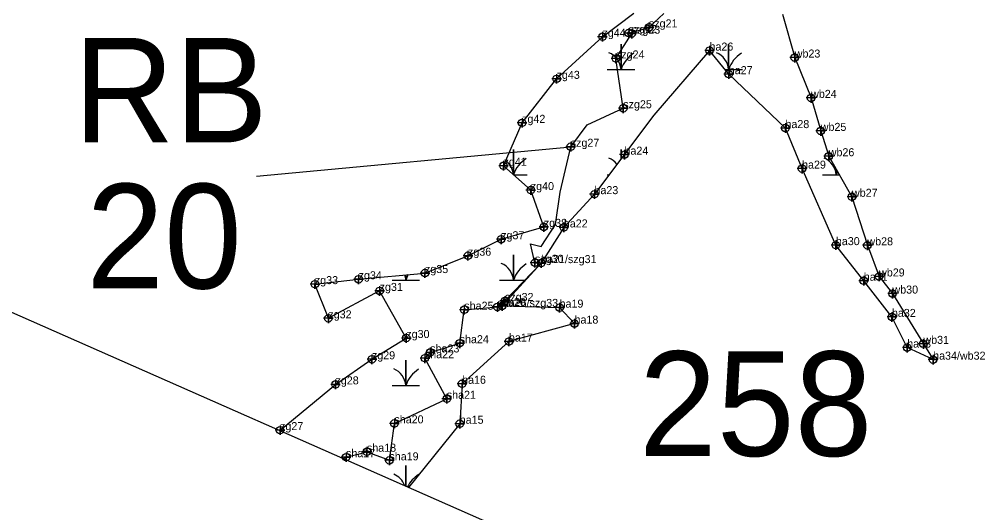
# Model space of a CAD drawing. Extents: x 2071991 to 2268989, y 436479 to 469629.
# Drawn here: x 2217397 to 2217992, y 438334 to 438642 of the extents above; entities that cross this region are included whole.
import ezdxf

# ---------------------------------------------------------------- set-up
doc = ezdxf.new("R2010")
doc.units = 0
for name, color, linetype in [('approx_PSA', 7, 'Continuous'), ('Default', 7, 'Continuous'), ('Exist Environmental Wetland Boundary', 7, 'Continuous'), ('Exist Environmental Wetland Boundary Cogo Comment', 7, 'Continuous'), ('Exist Environmental Wetland Boundary Cogo Point CELL', 7, 'Continuous'), ('Exist Hydro Jurisdictional Stream or Body of Water NEU Mitigable', 7, 'Continuous'), ('Exist Hydro Jurisdictional Stream or Body of Water NEU Mitigable Cogo Comment', 7, 'Continuous'), ('Exist Hydro Jurisdictional Stream or Body of Water NEU Mitigable Cogo Point CELL', 7, 'Continuous'), ('Exist Hydro Swamp or Marsh', 7, 'Continuous')]:
    doc.layers.add(name, color=color, linetype=linetype)

msp = doc.modelspace()

# ---------------------------------------------------------------- linework, layer by layer
at = {"layer": 'approx_PSA'}
msp.add_line((2217940.85, 438216.78), (2217222.14, 438533.73), dxfattribs=at)
at = {"layer": 'Default'}
msp.add_line((2217544.84, 438543.82), (2217741.11, 438562.25), dxfattribs=at)
at = {"layer": 'Exist Environmental Wetland Boundary'}
for points in [[(2217559.29, 438385.05), (2217559.58, 438385.27), (2217594.21, 438413.84), (2217616.96, 438429.52), (2217638.44, 438442.8), (2217621.77, 438472.21), (2217589.75, 438455.1), (2217581.34, 438476.45), (2217608.66, 438479.49), (2217650.1, 438483.36), (2217676.96, 438494.19), (2217697.67, 438504.47), (2217724.32, 438512.19), (2217716.18, 438535.18), (2217699.13, 438550.35), (2217710.75, 438577.17), (2217732.28, 438604.63), (2217760.94, 438630.93), (2217780.52, 438645.68)], [(2217873.28, 438645.11), (2217881.02, 438617.93), (2217891.24, 438592.74), (2217897.26, 438572.14), (2217902.25, 438556.31), (2217916.77, 438530.99), (2217926.41, 438500.68), (2217933.69, 438481.24), (2217942.06, 438470.55), (2217961.38, 438439.14), (2217967.44, 438429.29), (2217951.26, 438436.82), (2217941.72, 438455.97), (2217924.13, 438478.56), (2217906.71, 438500.8), (2217885.6, 438548.57), (2217875.21, 438573.89), (2217839.82, 438607.56), (2217827.79, 438622.29), (2217792.98, 438581.97), (2217755.94, 438532.64), (2217736.81, 438511.86), (2217722.64, 438489.58), (2217698.23, 438462.84), (2217734.16, 438461.77), (2217743.49, 438451.8), (2217702.54, 438440.61), (2217673.28, 438414.22), (2217671.8, 438389.27), (2217639.89, 438349.5)]]:
    msp.add_lwpolyline(points, dxfattribs=at)
at = {"layer": 'Exist Environmental Wetland Boundary Cogo Point CELL'}
for points in [[(2217760.94, 438633.93), (2217760.94, 438627.93), (2217760.94, 438630.93), (2217763.94, 438630.93), (2217757.94, 438630.93)], [(2217827.79, 438625.29), (2217827.79, 438619.29), (2217827.79, 438622.29), (2217830.79, 438622.29), (2217824.79, 438622.29)], [(2217881.02, 438620.93), (2217881.02, 438614.93), (2217881.02, 438617.93), (2217884.02, 438617.93), (2217878.02, 438617.93)], [(2217732.28, 438607.63), (2217732.28, 438601.63), (2217732.28, 438604.63), (2217735.28, 438604.63), (2217729.28, 438604.63)], [(2217839.82, 438610.56), (2217839.82, 438604.56), (2217839.82, 438607.56), (2217842.82, 438607.56), (2217836.82, 438607.56)], [(2217891.24, 438595.74), (2217891.24, 438589.74), (2217891.24, 438592.74), (2217894.24, 438592.74), (2217888.24, 438592.74)], [(2217710.75, 438580.17), (2217710.75, 438574.17), (2217710.75, 438577.17), (2217713.75, 438577.17), (2217707.75, 438577.17)], [(2217875.21, 438576.89), (2217875.21, 438570.89), (2217875.21, 438573.89), (2217878.21, 438573.89), (2217872.21, 438573.89)], [(2217897.26, 438575.14), (2217897.26, 438569.14), (2217897.26, 438572.14), (2217900.26, 438572.14), (2217894.26, 438572.14)], [(2217774.68, 438560.3), (2217774.68, 438554.3), (2217774.68, 438557.3), (2217777.68, 438557.3), (2217771.68, 438557.3)], [(2217902.25, 438559.31), (2217902.25, 438553.31), (2217902.25, 438556.31), (2217905.25, 438556.31), (2217899.25, 438556.31)], [(2217699.13, 438553.35), (2217699.13, 438547.35), (2217699.13, 438550.35), (2217702.13, 438550.35), (2217696.13, 438550.35)], [(2217885.6, 438551.57), (2217885.6, 438545.57), (2217885.6, 438548.57), (2217888.6, 438548.57), (2217882.6, 438548.57)], [(2217716.18, 438538.18), (2217716.18, 438532.18), (2217716.18, 438535.18), (2217719.18, 438535.18), (2217713.18, 438535.18)], [(2217755.94, 438535.64), (2217755.94, 438529.64), (2217755.94, 438532.64), (2217758.94, 438532.64), (2217752.94, 438532.64)], [(2217916.77, 438533.99), (2217916.77, 438527.99), (2217916.77, 438530.99), (2217919.77, 438530.99), (2217913.77, 438530.99)], [(2217724.32, 438515.19), (2217724.32, 438509.19), (2217724.32, 438512.19), (2217727.32, 438512.19), (2217721.32, 438512.19)], [(2217736.81, 438514.86), (2217736.81, 438508.86), (2217736.81, 438511.86), (2217739.81, 438511.86), (2217733.81, 438511.86)], [(2217697.67, 438507.47), (2217697.67, 438501.47), (2217697.67, 438504.47), (2217700.67, 438504.47), (2217694.67, 438504.47)], [(2217906.71, 438503.8), (2217906.71, 438497.8), (2217906.71, 438500.8), (2217909.71, 438500.8), (2217903.71, 438500.8)], [(2217926.41, 438503.68), (2217926.41, 438497.68), (2217926.41, 438500.68), (2217929.41, 438500.68), (2217923.41, 438500.68)], [(2217676.96, 438497.19), (2217676.96, 438491.19), (2217676.96, 438494.19), (2217679.96, 438494.19), (2217673.96, 438494.19)], [(2217722.64, 438492.58), (2217722.64, 438486.58), (2217722.64, 438489.58), (2217725.64, 438489.58), (2217719.64, 438489.58)], [(2217650.1, 438486.36), (2217650.1, 438480.36), (2217650.1, 438483.36), (2217653.1, 438483.36), (2217647.1, 438483.36)], [(2217608.66, 438482.49), (2217608.66, 438476.49), (2217608.66, 438479.49), (2217611.66, 438479.49), (2217605.66, 438479.49)], [(2217924.13, 438481.56), (2217924.13, 438475.56), (2217924.13, 438478.56), (2217927.13, 438478.56), (2217921.13, 438478.56)], [(2217933.69, 438484.24), (2217933.69, 438478.24), (2217933.69, 438481.24), (2217936.69, 438481.24), (2217930.69, 438481.24)], [(2217581.34, 438479.45), (2217581.34, 438473.45), (2217581.34, 438476.45), (2217584.34, 438476.45), (2217578.34, 438476.45)], [(2217621.77, 438475.21), (2217621.77, 438469.21), (2217621.77, 438472.21), (2217624.77, 438472.21), (2217618.77, 438472.21)], [(2217942.06, 438473.55), (2217942.06, 438467.55), (2217942.06, 438470.55), (2217945.06, 438470.55), (2217939.06, 438470.55)], [(2217698.23, 438465.84), (2217698.23, 438459.84), (2217698.23, 438462.84), (2217701.23, 438462.84), (2217695.23, 438462.84)], [(2217734.16, 438464.77), (2217734.16, 438458.77), (2217734.16, 438461.77), (2217737.16, 438461.77), (2217731.16, 438461.77)], [(2217589.75, 438458.1), (2217589.75, 438452.1), (2217589.75, 438455.1), (2217592.75, 438455.1), (2217586.75, 438455.1)], [(2217941.72, 438458.97), (2217941.72, 438452.97), (2217941.72, 438455.97), (2217944.72, 438455.97), (2217938.72, 438455.97)], [(2217743.49, 438454.8), (2217743.49, 438448.8), (2217743.49, 438451.8), (2217746.49, 438451.8), (2217740.49, 438451.8)], [(2217638.44, 438445.8), (2217638.44, 438439.8), (2217638.44, 438442.8), (2217641.44, 438442.8), (2217635.44, 438442.8)], [(2217702.54, 438443.61), (2217702.54, 438437.61), (2217702.54, 438440.61), (2217705.54, 438440.61), (2217699.54, 438440.61)], [(2217951.26, 438439.82), (2217951.26, 438433.82), (2217951.26, 438436.82), (2217954.26, 438436.82), (2217948.26, 438436.82)], [(2217961.38, 438442.14), (2217961.38, 438436.14), (2217961.38, 438439.14), (2217964.38, 438439.14), (2217958.38, 438439.14)], [(2217616.96, 438432.52), (2217616.96, 438426.52), (2217616.96, 438429.52), (2217619.96, 438429.52), (2217613.96, 438429.52)], [(2217967.44, 438432.29), (2217967.44, 438426.29), (2217967.44, 438429.29), (2217970.44, 438429.29), (2217964.44, 438429.29)], [(2217594.21, 438416.84), (2217594.21, 438410.84), (2217594.21, 438413.84), (2217597.21, 438413.84), (2217591.21, 438413.84)], [(2217673.28, 438417.22), (2217673.28, 438411.22), (2217673.28, 438414.22), (2217676.28, 438414.22), (2217670.28, 438414.22)], [(2217671.8, 438392.27), (2217671.8, 438386.27), (2217671.8, 438389.27), (2217674.8, 438389.27), (2217668.8, 438389.27)], [(2217559.58, 438388.27), (2217559.58, 438382.27), (2217559.58, 438385.27), (2217562.58, 438385.27), (2217556.58, 438385.27)]]:
    msp.add_lwpolyline(points, dxfattribs=at)
for centre in [(2217760.94, 438630.93), (2217827.79, 438622.29), (2217881.02, 438617.93), (2217732.28, 438604.63), (2217839.82, 438607.56), (2217891.24, 438592.74), (2217710.75, 438577.17), (2217875.21, 438573.89), (2217897.26, 438572.14), (2217774.68, 438557.3), (2217902.25, 438556.31), (2217699.13, 438550.35), (2217885.6, 438548.57), (2217716.18, 438535.18), (2217755.94, 438532.64), (2217916.77, 438530.99), (2217724.32, 438512.19), (2217736.81, 438511.86), (2217697.67, 438504.47), (2217906.71, 438500.8), (2217926.41, 438500.68), (2217676.96, 438494.19), (2217722.64, 438489.58), (2217608.66, 438479.49), (2217650.1, 438483.36), (2217924.13, 438478.56), (2217933.69, 438481.24), (2217581.34, 438476.45), (2217621.77, 438472.21), (2217942.06, 438470.55), (2217698.23, 438462.84), (2217734.16, 438461.77), (2217589.75, 438455.1), (2217941.72, 438455.97), (2217743.49, 438451.8), (2217638.44, 438442.8), (2217702.54, 438440.61), (2217951.26, 438436.82), (2217961.38, 438439.14), (2217616.96, 438429.52), (2217967.44, 438429.29), (2217594.21, 438413.84), (2217673.28, 438414.22), (2217671.8, 438389.27), (2217559.58, 438385.27)]:
    msp.add_circle(centre, 2.34, dxfattribs=at)
at = {"layer": 'Exist Hydro Jurisdictional Stream or Body of Water NEU Mitigable'}
msp.add_lwpolyline([(2217598.72, 438367.66), (2217600.81, 438368.38), (2217613.85, 438371.78), (2217627.9, 438366.42), (2217631.01, 438389.51), (2217663.72, 438404.86), (2217650.03, 438430.19), (2217653.35, 438433.79), (2217671.77, 438439.56), (2217674.66, 438460.46), (2217695.34, 438462.22), (2217700.03, 438465.94), (2217722.64, 438489.58), (2217718.8, 438489.79), (2217715.94, 438501.57), (2217722.61, 438499.98), (2217731.52, 438513.6), (2217734.44, 438533.91), (2217741.11, 438562.25), (2217751.33, 438575.89), (2217773.92, 438586.27), (2217769.35, 438617.37), (2217779.18, 438632.86), (2217777.31, 438633.2), (2217789.94, 438636.76), (2217799.31, 438645.52)], dxfattribs=at)
at = {"layer": 'Exist Hydro Jurisdictional Stream or Body of Water NEU Mitigable Cogo Point CELL'}
for points in [[(2217777.31, 438636.2), (2217777.31, 438630.2), (2217777.31, 438633.2), (2217780.31, 438633.2), (2217774.31, 438633.2)], [(2217779.18, 438635.86), (2217779.18, 438629.86), (2217779.18, 438632.86), (2217782.18, 438632.86), (2217776.18, 438632.86)], [(2217789.94, 438639.76), (2217789.94, 438633.76), (2217789.94, 438636.76), (2217792.94, 438636.76), (2217786.94, 438636.76)], [(2217769.35, 438620.37), (2217769.35, 438614.37), (2217769.35, 438617.37), (2217772.35, 438617.37), (2217766.35, 438617.37)], [(2217773.92, 438589.27), (2217773.92, 438583.27), (2217773.92, 438586.27), (2217776.92, 438586.27), (2217770.92, 438586.27)], [(2217741.11, 438565.25), (2217741.11, 438559.25), (2217741.11, 438562.25), (2217744.11, 438562.25), (2217738.11, 438562.25)], [(2217718.8, 438492.79), (2217718.8, 438486.79), (2217718.8, 438489.79), (2217721.8, 438489.79), (2217715.8, 438489.79)], [(2217700.03, 438468.94), (2217700.03, 438462.94), (2217700.03, 438465.94), (2217703.03, 438465.94), (2217697.03, 438465.94)], [(2217674.66, 438463.46), (2217674.66, 438457.46), (2217674.66, 438460.46), (2217677.66, 438460.46), (2217671.66, 438460.46)], [(2217695.34, 438465.22), (2217695.34, 438459.22), (2217695.34, 438462.22), (2217698.34, 438462.22), (2217692.34, 438462.22)], [(2217671.77, 438442.56), (2217671.77, 438436.56), (2217671.77, 438439.56), (2217674.77, 438439.56), (2217668.77, 438439.56)], [(2217650.03, 438433.19), (2217650.03, 438427.19), (2217650.03, 438430.19), (2217653.03, 438430.19), (2217647.03, 438430.19)], [(2217653.35, 438436.79), (2217653.35, 438430.79), (2217653.35, 438433.79), (2217656.35, 438433.79), (2217650.35, 438433.79)], [(2217663.72, 438407.86), (2217663.72, 438401.86), (2217663.72, 438404.86), (2217666.72, 438404.86), (2217660.72, 438404.86)], [(2217631.01, 438392.51), (2217631.01, 438386.51), (2217631.01, 438389.51), (2217634.01, 438389.51), (2217628.01, 438389.51)], [(2217613.85, 438374.78), (2217613.85, 438368.78), (2217613.85, 438371.78), (2217616.85, 438371.78), (2217610.85, 438371.78)], [(2217600.81, 438371.38), (2217600.81, 438365.38), (2217600.81, 438368.38), (2217603.81, 438368.38), (2217597.81, 438368.38)], [(2217627.9, 438369.42), (2217627.9, 438363.42), (2217627.9, 438366.42), (2217630.9, 438366.42), (2217624.9, 438366.42)]]:
    msp.add_lwpolyline(points, dxfattribs=at)
for centre in [(2217777.31, 438633.2), (2217779.18, 438632.86), (2217789.94, 438636.76), (2217769.35, 438617.37), (2217773.92, 438586.27), (2217741.11, 438562.25), (2217718.8, 438489.79), (2217674.66, 438460.46), (2217695.34, 438462.22), (2217700.03, 438465.94), (2217671.77, 438439.56), (2217653.35, 438433.79), (2217650.03, 438430.19), (2217663.72, 438404.86), (2217631.01, 438389.51), (2217613.85, 438371.78), (2217600.81, 438368.38), (2217627.9, 438366.42)]:
    msp.add_circle(centre, 2.34, dxfattribs=at)
at = {"layer": 'Exist Hydro Swamp or Marsh'}
for p, q in [((2217705.5, 438544.68), (2217713.93, 438544.68)), ((2217763.93, 438544.68), (2217764.98, 438544.68))]:
    msp.add_line(p, q, dxfattribs=at)
for points in [[(2217763.93, 438610.46), (2217772.53, 438610.46), (2217772.53, 438626.24), (2217772.53, 438610.46), (2217781.13, 438610.46)], [(2217837.45, 438610.46), (2217839.74, 438610.46), (2217839.74, 438626.24), (2217839.74, 438610.46), (2217848.34, 438610.46)], [(2217705.33, 438544.83), (2217705.33, 438560.46), (2217705.33, 438544.83)], [(2217772.53, 438554.74), (2217772.53, 438560.46), (2217772.53, 438554.74)], [(2217898.34, 438544.68), (2217906.94, 438544.68), (2217906.94, 438548.14)], [(2217906.94, 438548.14), (2217906.94, 438544.68), (2217908.92, 438544.68)], [(2217696.73, 438478.9), (2217705.33, 438478.9), (2217705.33, 438494.68), (2217705.33, 438478.9), (2217712.89, 438478.9)], [(2217629.52, 438478.9), (2217638.13, 438478.9), (2217638.13, 438482.24)], [(2217638.13, 438482.24), (2217638.13, 438478.9), (2217646.73, 438478.9)], [(2217629.52, 438413.12), (2217638.13, 438413.12), (2217638.13, 438428.9), (2217638.13, 438413.12), (2217646.73, 438413.12)], [(2217638.13, 438350.28), (2217638.13, 438363.12), (2217638.13, 438350.28)]]:
    msp.add_lwpolyline(points, dxfattribs=at)
for centre, radius, start, end in [((2217760.27, 438609.58), 12.3, 4.14034, 67.53497), ((2217790.77, 438604.4), 19.22, 122.12745, 161.62219), ((2217827.47, 438609.58), 12.3, 4.14034, 67.53497), ((2217857.98, 438604.4), 19.22, 122.12745, 161.62219), ((2217693.06, 438543.79), 12.3, 4.90369, 52.63639), ((2217723.57, 438538.62), 19.22, 122.12745, 161.2546), ((2217760.27, 438543.79), 12.3, 37.83312, 67.53497), ((2217894.67, 438543.79), 12.3, 4.14034, 67.53497), ((2217925.18, 438538.62), 19.22, 155.07473, 161.62219), ((2217693.06, 438478.01), 12.3, 4.14034, 67.53497), ((2217723.57, 438472.84), 19.22, 122.12745, 161.62219), ((2217625.86, 438478.01), 12.3, 4.14034, 19.77671), ((2217656.37, 438472.84), 19.22, 150.23165, 161.62219), ((2217625.86, 438412.23), 12.3, 4.14034, 67.53497), ((2217656.37, 438407.06), 19.22, 122.12745, 161.62219), ((2217625.86, 438346.45), 12.3, 19.60086, 67.53497), ((2217656.37, 438341.28), 19.22, 122.12745, 153.60163)]:
    msp.add_arc(centre, radius, start, end, dxfattribs=at)

# ---------------------------------------------------------------- texts
at = {"layer": 'Default'}
for s, p in [('RB', (2217430.54, 438564.89)), ('20', (2217438.59, 438473.74)), ('258', (2217783.77, 438369.14))]:
    msp.add_text(s, height=65.34, dxfattribs=at).set_placement(p)
at = {"layer": 'Exist Environmental Wetland Boundary Cogo Comment'}
for s, p in [('zg44', (2217760.94, 438630.93)), ('ha26', (2217827.79, 438622.29)), ('wb23', (2217881.02, 438617.93)), ('ha27', (2217839.82, 438607.56)), ('zg43', (2217732.28, 438604.63)), ('wb24', (2217891.24, 438592.74)), ('zg42', (2217710.75, 438577.17)), ('ha28', (2217875.21, 438573.89)), ('wb25', (2217897.26, 438572.14)), ('ha24', (2217774.68, 438557.3)), ('wb26', (2217902.25, 438556.31)), ('zg41', (2217699.13, 438550.35)), ('ha29', (2217885.6, 438548.57)), ('zg40', (2217716.18, 438535.18)), ('ha23', (2217755.94, 438532.64)), ('wb27', (2217916.77, 438530.99)), ('zg37', (2217697.67, 438504.47)), ('ha30', (2217906.71, 438500.8)), ('wb28', (2217926.41, 438500.68)), ('zg36', (2217676.96, 438494.19)), ('szg30', (2217718.8, 438489.79)), ('zg35', (2217650.1, 438483.36)), ('wb29', (2217933.69, 438481.24)), ('zg33', (2217581.34, 438476.45)), ('zg34', (2217608.66, 438479.49)), ('ha31', (2217924.13, 438478.56)), ('zg31', (2217621.77, 438472.21)), ('wb30', (2217942.06, 438470.55)), ('ha20', (2217698.23, 438462.84)), ('ha19', (2217734.16, 438461.77)), ('zg32', (2217589.75, 438455.1)), ('ha18', (2217743.49, 438451.8)), ('ha32', (2217941.72, 438455.97)), ('zg30', (2217638.44, 438442.8)), ('ha17', (2217702.54, 438440.61)), ('ha33', (2217951.26, 438436.82)), ('wb31', (2217961.38, 438439.14)), ('zg29', (2217616.96, 438429.52)), ('ha34/wb32', (2217967.44, 438429.29)), ('zg28', (2217594.21, 438413.84)), ('ha16', (2217673.28, 438414.22)), ('ha15', (2217671.8, 438389.27)), ('zg27', (2217559.58, 438385.27))]:
    msp.add_text(s, height=5, dxfattribs=at).set_placement(p)
at = {"layer": 'Exist Hydro Jurisdictional Stream or Body of Water NEU Mitigable Cogo Comment'}
for s, p in [('szg21', (2217789.94, 438636.76)), ('szg22', (2217777.31, 438633.2)), ('szg23', (2217779.18, 438632.86)), ('szg24', (2217769.35, 438617.37)), ('szg25', (2217773.92, 438586.27)), ('szg27', (2217741.11, 438562.25)), ('zg38', (2217724.32, 438512.19)), ('ha22', (2217736.81, 438511.86)), ('ha21/szg31', (2217722.64, 438489.58)), ('szg32', (2217700.03, 438465.94)), ('sha25', (2217674.66, 438460.46)), ('sha26/szg33', (2217695.34, 438462.22)), ('sha24', (2217671.77, 438439.56)), ('sha23', (2217653.35, 438433.79)), ('sha22', (2217650.03, 438430.19)), ('sha21', (2217663.72, 438404.86)), ('sha20', (2217631.01, 438389.51)), ('sha17', (2217600.81, 438368.38)), ('sha18', (2217613.85, 438371.78)), ('sha19', (2217627.9, 438366.42))]:
    msp.add_text(s, height=5, dxfattribs=at).set_placement(p)

doc.saveas('drawing.dxf')
